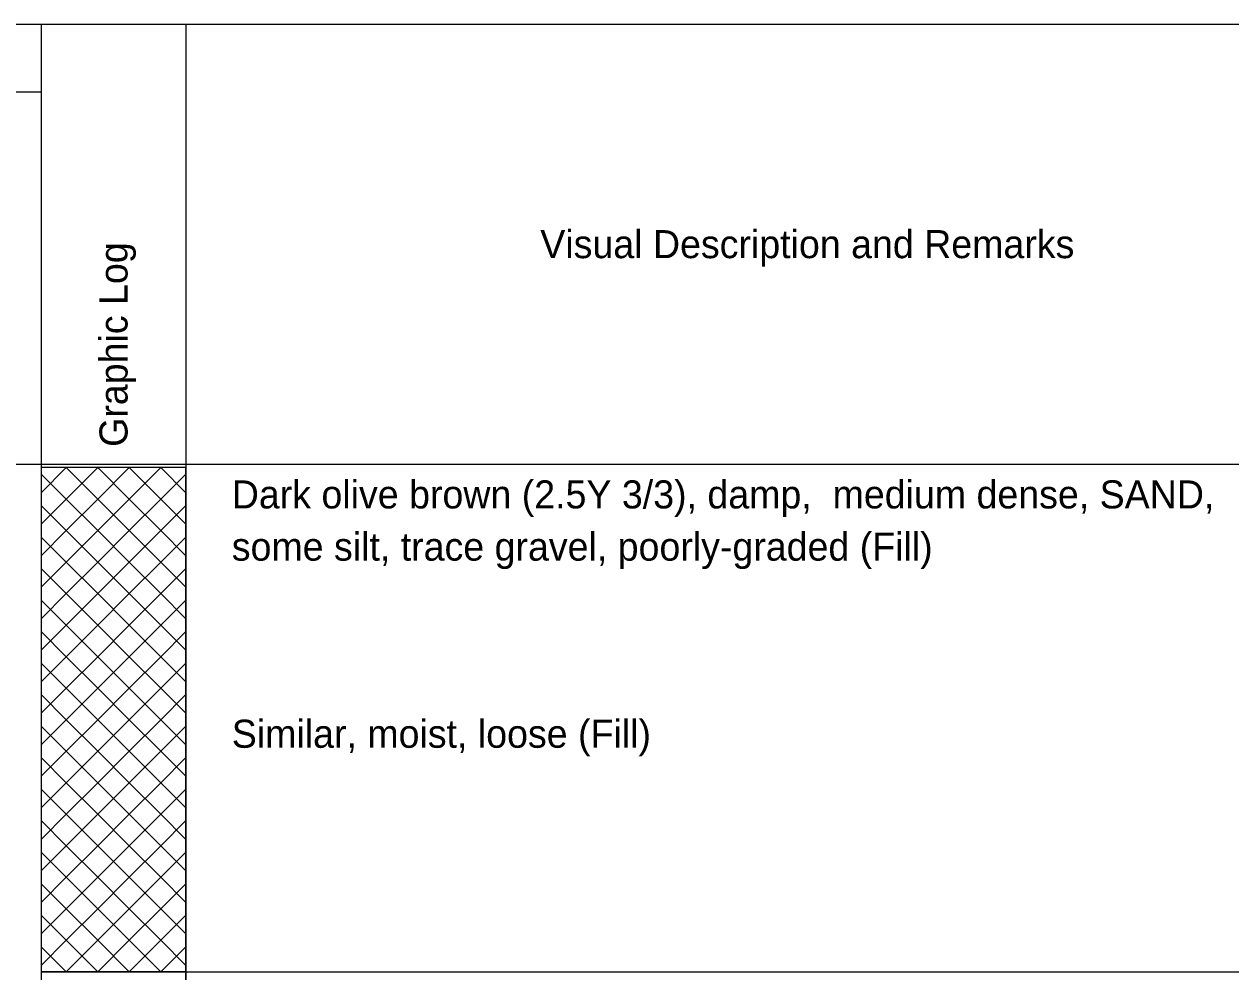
# Model space of a CAD drawing. Extents: x 9419 to 9552, y 6780 to 6865.
# Drawn here: x 9476.01 to 9485.59, y 6843.01 to 6850.53 of the extents above; entities that cross this region are included whole.
import ezdxf

# ---------------------------------------------------------------- set-up
doc = ezdxf.new("R2010")
doc.units = 0
doc.layers.add('7', color=7, linetype='Continuous')
doc.layers.add('8', color=7, linetype='Continuous')

msp = doc.modelspace()

# ---------------------------------------------------------------- linework, layer by layer
at = {"layer": '7'}
for p, q in [((9476.1476, 6847.0106), (9476.1476, 6843.0106)), ((9477.2959, 6847.0106), (9476.1476, 6847.0106)), ((9477.2959, 6843.0106), (9477.2959, 6847.0106)), ((9476.1476, 6843.0106), (9477.2959, 6843.0106)), ((9476.1476, 6843.0106), (9476.1476, 6840.0106)), ((9477.2959, 6843.0106), (9476.1476, 6843.0106)), ((9477.2959, 6840.0106), (9477.2959, 6843.0106)), ((9477.2959, 6843.0106), (9488.4482, 6843.0106))]:
    msp.add_line(p, q, dxfattribs=at)
for points in [[(9460.2824, 6850.5283), (9491.7784, 6850.5283)], [(9476.1476, 6850.5283), (9476.1476, 6821.9829)], [(9477.2959, 6850.5283), (9477.2959, 6821.9829)], [(9461.4001, 6849.9919), (9476.1476, 6849.9919)], [(9460.2824, 6847.0384), (9491.7784, 6847.0384)]]:
    msp.add_lwpolyline(points, dxfattribs=at)
at = {"layer": '8'}
for p, q in [((9476.1476, 6846.8115), (9476.3468, 6847.0106)), ((9476.5968, 6846.7606), (9476.3468, 6847.0106)), ((9476.3468, 6846.7606), (9476.5968, 6847.0106)), ((9476.8468, 6846.7606), (9476.5968, 6847.0106)), ((9476.5968, 6846.7606), (9476.8468, 6847.0106)), ((9477.0968, 6846.7606), (9476.8468, 6847.0106)), ((9476.8468, 6846.7606), (9477.0968, 6847.0106)), ((9477.2959, 6846.8115), (9477.0968, 6847.0106)), ((9476.3468, 6846.7606), (9476.1476, 6846.9597)), ((9477.0968, 6846.7606), (9477.2959, 6846.9597)), ((9476.1476, 6846.5615), (9476.3468, 6846.7606)), ((9476.5968, 6846.5106), (9476.3468, 6846.7606)), ((9476.3468, 6846.5106), (9476.5968, 6846.7606)), ((9476.8468, 6846.5106), (9476.5968, 6846.7606)), ((9476.5968, 6846.5106), (9476.8468, 6846.7606)), ((9477.0968, 6846.5106), (9476.8468, 6846.7606)), ((9476.8468, 6846.5106), (9477.0968, 6846.7606)), ((9477.2959, 6846.5615), (9477.0968, 6846.7606)), ((9476.3468, 6846.5106), (9476.1476, 6846.7097)), ((9477.0968, 6846.5106), (9477.2959, 6846.7097)), ((9476.1476, 6846.3115), (9476.3468, 6846.5106)), ((9476.3468, 6846.2606), (9476.1476, 6846.4597)), ((9476.5968, 6846.2606), (9476.3468, 6846.5106)), ((9476.3468, 6846.2606), (9476.5968, 6846.5106)), ((9476.8468, 6846.2606), (9476.5968, 6846.5106)), ((9476.5968, 6846.2606), (9476.8468, 6846.5106)), ((9477.0968, 6846.2606), (9476.8468, 6846.5106)), ((9476.8468, 6846.2606), (9477.0968, 6846.5106)), ((9477.2959, 6846.3115), (9477.0968, 6846.5106)), ((9477.0968, 6846.2606), (9477.2959, 6846.4597)), ((9476.1476, 6846.0615), (9476.3468, 6846.2606)), ((9476.5968, 6846.0106), (9476.3468, 6846.2606)), ((9476.3468, 6846.0106), (9476.5968, 6846.2606)), ((9476.8468, 6846.0106), (9476.5968, 6846.2606)), ((9476.5968, 6846.0106), (9476.8468, 6846.2606)), ((9477.0968, 6846.0106), (9476.8468, 6846.2606)), ((9476.8468, 6846.0106), (9477.0968, 6846.2606)), ((9477.2959, 6846.0615), (9477.0968, 6846.2606)), ((9476.3468, 6846.0106), (9476.1476, 6846.2097)), ((9477.0968, 6846.0106), (9477.2959, 6846.2097)), ((9476.1476, 6845.8115), (9476.3468, 6846.0106)), ((9476.3468, 6845.7606), (9476.1476, 6845.9597)), ((9476.5968, 6845.7606), (9476.3468, 6846.0106)), ((9476.3468, 6845.7606), (9476.5968, 6846.0106)), ((9476.8468, 6845.7606), (9476.5968, 6846.0106)), ((9476.5968, 6845.7606), (9476.8468, 6846.0106)), ((9477.0968, 6845.7606), (9476.8468, 6846.0106)), ((9476.8468, 6845.7606), (9477.0968, 6846.0106)), ((9477.2959, 6845.8115), (9477.0968, 6846.0106)), ((9477.0968, 6845.7606), (9477.2959, 6845.9597)), ((9476.1476, 6845.5615), (9476.3468, 6845.7606)), ((9476.5968, 6845.5106), (9476.3468, 6845.7606)), ((9476.3468, 6845.5106), (9476.5968, 6845.7606)), ((9476.8468, 6845.5106), (9476.5968, 6845.7606)), ((9476.5968, 6845.5106), (9476.8468, 6845.7606)), ((9477.0968, 6845.5106), (9476.8468, 6845.7606)), ((9476.8468, 6845.5106), (9477.0968, 6845.7606)), ((9477.2959, 6845.5615), (9477.0968, 6845.7606)), ((9476.3468, 6845.5106), (9476.1476, 6845.7097)), ((9477.0968, 6845.5106), (9477.2959, 6845.7097)), ((9476.1476, 6845.3115), (9476.3468, 6845.5106)), ((9476.5968, 6845.2606), (9476.3468, 6845.5106)), ((9476.3468, 6845.2606), (9476.5968, 6845.5106)), ((9476.8468, 6845.2606), (9476.5968, 6845.5106)), ((9476.5968, 6845.2606), (9476.8468, 6845.5106)), ((9477.0968, 6845.2606), (9476.8468, 6845.5106)), ((9476.8468, 6845.2606), (9477.0968, 6845.5106)), ((9477.2959, 6845.3115), (9477.0968, 6845.5106)), ((9476.3468, 6845.2606), (9476.1476, 6845.4598)), ((9477.0968, 6845.2606), (9477.2959, 6845.4598)), ((9476.1476, 6845.0615), (9476.3468, 6845.2606)), ((9476.3468, 6845.0106), (9476.1476, 6845.2097)), ((9476.5968, 6845.0106), (9476.3468, 6845.2606)), ((9476.3468, 6845.0106), (9476.5968, 6845.2606)), ((9476.8468, 6845.0106), (9476.5968, 6845.2606)), ((9476.5968, 6845.0106), (9476.8468, 6845.2606)), ((9477.0968, 6845.0106), (9476.8468, 6845.2606)), ((9476.8468, 6845.0106), (9477.0968, 6845.2606)), ((9477.2959, 6845.0615), (9477.0968, 6845.2606)), ((9477.0968, 6845.0106), (9477.2959, 6845.2097)), ((9476.1476, 6844.8115), (9476.3468, 6845.0106)), ((9476.5968, 6844.7606), (9476.3468, 6845.0106)), ((9476.3468, 6844.7606), (9476.5968, 6845.0106)), ((9476.8468, 6844.7606), (9476.5968, 6845.0106)), ((9476.5968, 6844.7606), (9476.8468, 6845.0106)), ((9477.0968, 6844.7606), (9476.8468, 6845.0106)), ((9476.8468, 6844.7606), (9477.0968, 6845.0106)), ((9477.2959, 6844.8115), (9477.0968, 6845.0106)), ((9476.3468, 6844.7606), (9476.1476, 6844.9597)), ((9477.0968, 6844.7606), (9477.2959, 6844.9597)), ((9476.1476, 6844.5615), (9476.3468, 6844.7606)), ((9476.3468, 6844.5106), (9476.1476, 6844.7098)), ((9476.5968, 6844.5106), (9476.3468, 6844.7606)), ((9476.3468, 6844.5106), (9476.5968, 6844.7606)), ((9476.8468, 6844.5106), (9476.5968, 6844.7606)), ((9476.5968, 6844.5106), (9476.8468, 6844.7606)), ((9477.0968, 6844.5106), (9476.8468, 6844.7606)), ((9476.8468, 6844.5106), (9477.0968, 6844.7606)), ((9477.2959, 6844.5615), (9477.0968, 6844.7606)), ((9477.0968, 6844.5106), (9477.2959, 6844.7098)), ((9476.1476, 6844.3115), (9476.3468, 6844.5106)), ((9476.5968, 6844.2606), (9476.3468, 6844.5106)), ((9476.3468, 6844.2606), (9476.5968, 6844.5106)), ((9476.8468, 6844.2606), (9476.5968, 6844.5106)), ((9476.5968, 6844.2606), (9476.8468, 6844.5106)), ((9477.0968, 6844.2606), (9476.8468, 6844.5106)), ((9476.8468, 6844.2606), (9477.0968, 6844.5106)), ((9477.2959, 6844.3115), (9477.0968, 6844.5106)), ((9476.3468, 6844.2606), (9476.1476, 6844.4598)), ((9477.0968, 6844.2606), (9477.2959, 6844.4598)), ((9476.1476, 6844.0615), (9476.3468, 6844.2606)), ((9476.5968, 6844.0106), (9476.3468, 6844.2606)), ((9476.3468, 6844.0106), (9476.5968, 6844.2606)), ((9476.8468, 6844.0106), (9476.5968, 6844.2606)), ((9476.5968, 6844.0106), (9476.8468, 6844.2606)), ((9477.0968, 6844.0106), (9476.8468, 6844.2606)), ((9476.8468, 6844.0106), (9477.0968, 6844.2606)), ((9477.2959, 6844.0615), (9477.0968, 6844.2606)), ((9476.3468, 6844.0106), (9476.1476, 6844.2098)), ((9477.0968, 6844.0106), (9477.2959, 6844.2098)), ((9476.1476, 6843.8115), (9476.3468, 6844.0106)), ((9476.3468, 6843.7606), (9476.1476, 6843.9598)), ((9476.5968, 6843.7606), (9476.3468, 6844.0106)), ((9476.3468, 6843.7606), (9476.5968, 6844.0106)), ((9476.8468, 6843.7606), (9476.5968, 6844.0106)), ((9476.5968, 6843.7606), (9476.8468, 6844.0106)), ((9477.0968, 6843.7606), (9476.8468, 6844.0106)), ((9476.8468, 6843.7606), (9477.0968, 6844.0106)), ((9477.2959, 6843.8115), (9477.0968, 6844.0106)), ((9477.0968, 6843.7606), (9477.2959, 6843.9598)), ((9476.1476, 6843.5615), (9476.3468, 6843.7606)), ((9476.5968, 6843.5106), (9476.3468, 6843.7606)), ((9476.3468, 6843.5106), (9476.5968, 6843.7606)), ((9476.8468, 6843.5106), (9476.5968, 6843.7606)), ((9476.5968, 6843.5106), (9476.8468, 6843.7606)), ((9477.0968, 6843.5106), (9476.8468, 6843.7606)), ((9476.8468, 6843.5106), (9477.0968, 6843.7606)), ((9477.2959, 6843.5615), (9477.0968, 6843.7606)), ((9476.3468, 6843.5106), (9476.1476, 6843.7098)), ((9477.0968, 6843.5106), (9477.2959, 6843.7098)), ((9476.1476, 6843.3115), (9476.3468, 6843.5106)), ((9476.3468, 6843.2606), (9476.1476, 6843.4598)), ((9476.5968, 6843.2606), (9476.3468, 6843.5106)), ((9476.3468, 6843.2606), (9476.5968, 6843.5106)), ((9476.8468, 6843.2606), (9476.5968, 6843.5106)), ((9476.5968, 6843.2606), (9476.8468, 6843.5106)), ((9477.0968, 6843.2606), (9476.8468, 6843.5106)), ((9476.8468, 6843.2606), (9477.0968, 6843.5106)), ((9477.2959, 6843.3115), (9477.0968, 6843.5106)), ((9477.0968, 6843.2606), (9477.2959, 6843.4598)), ((9476.1476, 6843.0615), (9476.3468, 6843.2606)), ((9476.3468, 6843.0106), (9476.1476, 6843.2098)), ((9476.5968, 6843.0106), (9476.3468, 6843.2606)), ((9476.3468, 6843.0106), (9476.5968, 6843.2606)), ((9476.8468, 6843.0106), (9476.5968, 6843.2606)), ((9476.5968, 6843.0106), (9476.8468, 6843.2606)), ((9477.0968, 6843.0106), (9476.8468, 6843.2606)), ((9476.8468, 6843.0106), (9477.0968, 6843.2606)), ((9477.2959, 6843.0615), (9477.0968, 6843.2606)), ((9477.0968, 6843.0106), (9477.2959, 6843.2098))]:
    msp.add_line(p, q, dxfattribs=at)

# ---------------------------------------------------------------- texts
at = {"layer": '7'}
for s, height, p in [('Visual Description and Remarks', 0.222801, (9480.1093, 6848.6719)), ('Dark olive brown (2.5Y 3/3), damp,  medium dense, SAND,', 0.2228, (9477.6605, 6846.6865)), ('some silt, trace gravel, poorly-graded (Fill)', 0.2228, (9477.6605, 6846.2723)), ('Similar, moist, loose (Fill)', 0.2228, (9477.6605, 6844.7878))]:
    msp.add_text(s, height=height, dxfattribs=at).set_placement(p)
msp.add_text('Graphic Log', height=0.222801, rotation=90, dxfattribs=at).set_placement((9476.8332, 6847.1747))

doc.saveas('drawing.dxf')
